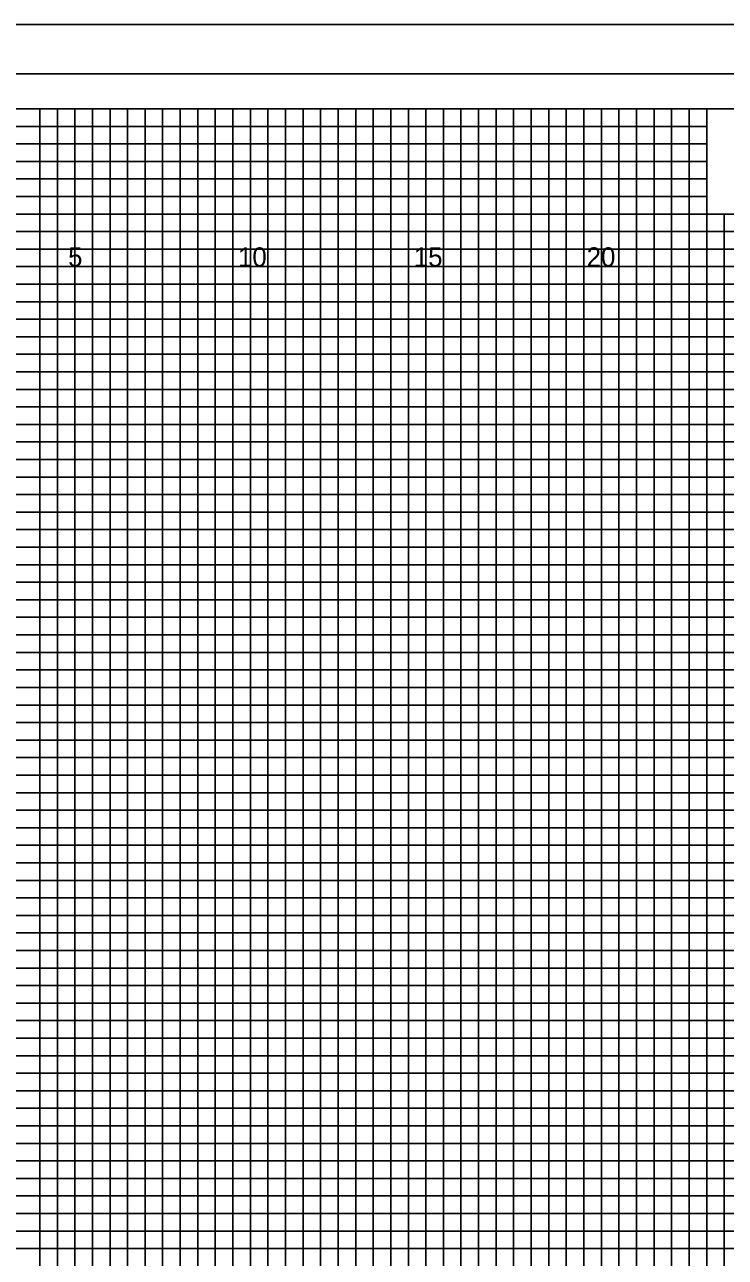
# Model space of a CAD drawing. Extents: x -4 to 103, y -2 to 209.
# Drawn here: x 54.82 to 74.78, y 32.25 to 67.4 of the extents above; entities that cross this region are included whole.
import ezdxf

# ---------------------------------------------------------------- set-up
doc = ezdxf.new("R2010")
doc.units = 0
for name, color, linetype in [('Exist XS Ground Line', 7, 'Continuous'), ('Old_Level_10', 7, 'Continuous'), ('Old_Level_3', 7, 'Continuous'), ('Old_Level_5', 7, 'Continuous'), ('Old_Level_8', 7, 'Continuous'), ('Prop XS Dump Level', 7, 'Continuous'), ('Prop XS Elevation Labels', 7, 'Continuous'), ('Prop XS Finish Grade', 7, 'Continuous')]:
    doc.layers.add(name, color=color, linetype=linetype)

msp = doc.modelspace()

# ---------------------------------------------------------------- linework, layer by layer
at = {"layer": 'Exist XS Ground Line'}
msp.add_lwpolyline([(103, 66), (-2.8, 66), (-2.8, -1), (103, -1)], close=True, dxfattribs=at)
at = {"layer": 'Old_Level_10'}
for p, q in [((56.25, 0), (56.25, 65)), ((58.75, 0), (58.75, 65)), ((61.25, 0), (61.25, 65)), ((63.75, 0), (63.75, 65)), ((66.25, 0), (66.25, 65)), ((68.75, 0), (68.75, 65)), ((71.25, 0), (71.25, 65)), ((73.75, 0), (73.75, 65)), ((0, 62.5), (74.25, 62.5)), ((0, 60), (102.5, 60)), ((0, 57.5), (102.5, 57.5)), ((0, 55), (102.5, 55)), ((0, 52.5), (102.5, 52.5)), ((0, 50), (102.5, 50)), ((0, 47.5), (102.5, 47.5)), ((0, 45), (102.5, 45)), ((0, 42.5), (102.5, 42.5)), ((0, 40), (102.5, 40)), ((0, 37.5), (102.5, 37.5)), ((0, 35), (102.5, 35)), ((0, 32.5), (102.5, 32.5))]:
    msp.add_line(p, q, dxfattribs=at)
at = {"layer": 'Old_Level_3'}
msp.add_line((-3.5, 67.4), (103.4, 67.4), dxfattribs=at)
at = {"layer": 'Old_Level_5'}
msp.add_lwpolyline([(103.4, 67.4), (-3.5, 67.4), (-3.5, -2.425), (103.4, -2.425)], close=True, dxfattribs=at)
at = {"layer": 'Old_Level_8'}
for points in [[(56.25, 0), (56.25, 65), (58.75, 65), (58.75, 0)], [(61.25, 0), (61.25, 65), (63.75, 65), (63.75, 0)], [(66.25, 0), (66.25, 65), (68.75, 65), (68.75, 0)], [(71.25, 0), (71.25, 65), (73.75, 65), (73.75, 0)], [(0, 62.5), (74.25, 62.5)], [(0, 57.5), (102.5, 57.5), (102.5, 60), (0, 60)], [(0, 52.5), (102.5, 52.5), (102.5, 55), (0, 55)], [(0, 47.5), (102.5, 47.5), (102.5, 50), (0, 50)], [(0, 42.5), (102.5, 42.5), (102.5, 45), (0, 45)], [(0, 37.5), (102.5, 37.5), (102.5, 40), (0, 40)], [(0, 32.5), (102.5, 32.5), (102.5, 35), (0, 35)]]:
    msp.add_lwpolyline(points, dxfattribs=at)
at = {"layer": 'Prop XS Dump Level'}
for points in [[(102.5, 65), (0, 65), (0, 0), (102.5, 0)], [(83.75, 65), (74.25, 65), (74.25, 62), (83.75, 62)]]:
    msp.add_lwpolyline(points, close=True, dxfattribs=at)
at = {"layer": 'Prop XS Finish Grade'}
for points in [[(55.25, 0), (55.25, 65), (55.75, 65), (55.75, 0)], [(56.75, 0), (56.75, 65), (57.25, 65), (57.25, 0)], [(57.75, 0), (57.75, 65), (58.25, 65), (58.25, 0)], [(59.25, 0), (59.25, 65), (59.75, 65), (59.75, 0)], [(60.25, 0), (60.25, 65), (60.75, 65), (60.75, 0)], [(61.75, 0), (61.75, 65), (62.25, 65), (62.25, 0)], [(62.75, 0), (62.75, 65), (63.25, 65), (63.25, 0)], [(64.25, 0), (64.25, 65), (64.75, 65), (64.75, 0)], [(65.25, 0), (65.25, 65), (65.75, 65), (65.75, 0)], [(66.75, 0), (66.75, 65), (67.25, 65), (67.25, 0)], [(67.75, 0), (67.75, 65), (68.25, 65), (68.25, 0)], [(69.25, 0), (69.25, 65)], [(69.25, 65), (69.75, 65), (69.75, 0)], [(70.25, 0), (70.25, 65), (70.75, 65), (70.75, 0)], [(71.75, 0), (71.75, 65), (72.25, 65), (72.25, 0)], [(72.75, 0), (72.75, 65), (73.25, 65), (73.25, 0)], [(0, 62), (0, 63), (74.25, 63), (74.25, 63.5), (0, 63.5), (0, 64), (74.25, 64), (74.25, 64.5), (0, 64.5)], [(0, 61.5), (102.5, 61.5), (102.5, 62), (0, 62)], [(74.25, 0), (74.25, 62), (74.75, 62), (74.75, 0)], [(0, 60.5), (102.5, 60.5), (102.5, 61), (0, 61)], [(0, 59), (102.5, 59), (102.5, 59.5), (0, 59.5)], [(0, 58), (102.5, 58), (102.5, 58.5), (0, 58.5)], [(0, 56.5), (102.5, 56.5), (102.5, 57), (0, 57)], [(0, 55.5), (102.5, 55.5), (102.5, 56), (0, 56)], [(0, 54), (102.5, 54), (102.5, 54.5), (0, 54.5)], [(0, 53), (102.5, 53), (102.5, 53.5), (0, 53.5)], [(0, 51.5), (102.5, 51.5), (102.5, 52), (0, 52)], [(0, 50.5), (102.5, 50.5), (102.5, 51), (0, 51)], [(0, 49), (102.5, 49), (102.5, 49.5), (0, 49.5)], [(0, 48), (102.5, 48), (102.5, 48.5), (0, 48.5)], [(0, 46.5), (102.5, 46.5), (102.5, 47), (0, 47)], [(0, 45.5), (102.5, 45.5), (102.5, 46), (0, 46)], [(0, 44), (102.5, 44), (102.5, 44.5), (0, 44.5)], [(0, 43), (102.5, 43), (102.5, 43.5), (0, 43.5)], [(0, 41.5), (102.5, 41.5), (102.5, 42), (0, 42)], [(0, 40.5), (102.5, 40.5), (102.5, 41), (0, 41)], [(0, 39), (102.5, 39), (102.5, 39.5), (0, 39.5)], [(0, 38), (102.5, 38), (102.5, 38.5), (0, 38.5)], [(0, 36.5), (102.5, 36.5), (102.5, 37), (0, 37)], [(0, 35.5), (102.5, 35.5), (102.5, 36), (0, 36)], [(0, 34), (102.5, 34), (102.5, 34.5), (0, 34.5)], [(0, 33), (102.5, 33), (102.5, 33.5), (0, 33.5)]]:
    msp.add_lwpolyline(points, dxfattribs=at)

# ---------------------------------------------------------------- texts
at = {"layer": 'Prop XS Elevation Labels'}
for s, p in [('5', (56.0574, 60.5)), ('10', (60.8971, 60.5)), ('15', (65.9057, 60.5)), ('20', (70.8312, 60.5))]:
    msp.add_text(s, height=0.55, dxfattribs=at).set_placement(p)

doc.saveas('drawing.dxf')
